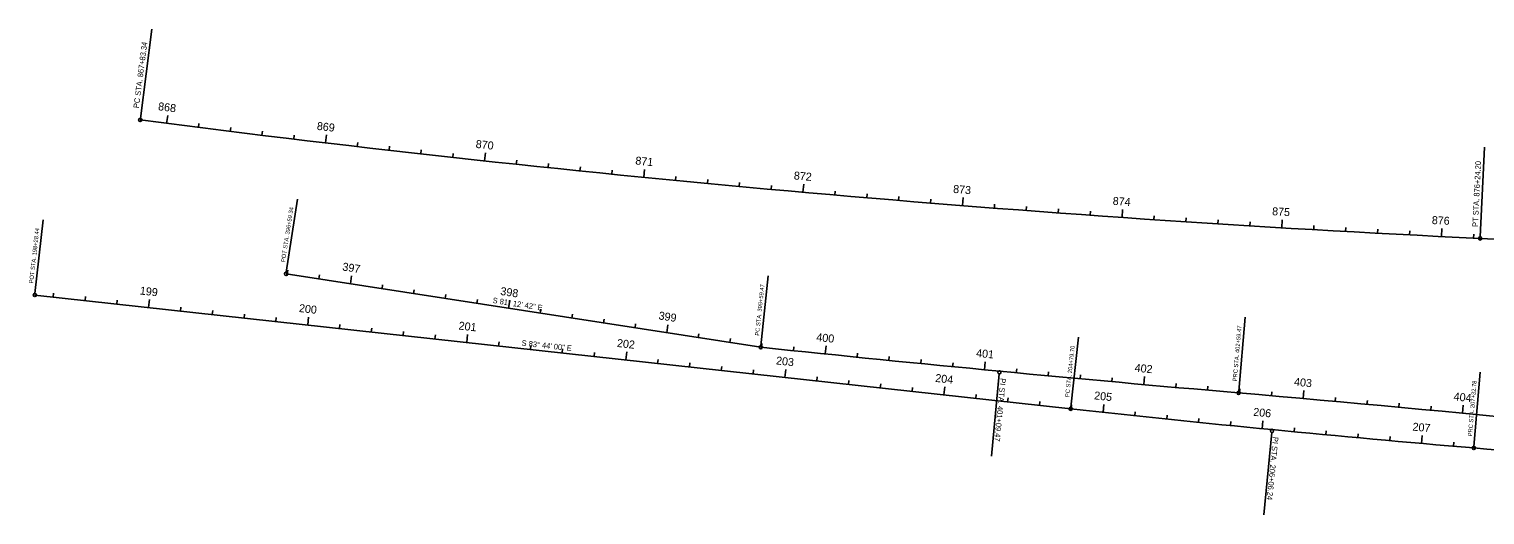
# Model space of a CAD drawing. Extents: x 919452 to 931278, y 583254 to 665650.
# Drawn here: x 925159 to 926069, y 636745 to 637048 of the extents above; entities that cross this region are included whole.
import ezdxf

# ---------------------------------------------------------------- set-up
doc = ezdxf.new("R2010")
doc.units = 0
for name, color, linetype in [('CLConst_dp', 7, 'Continuous'), ('CurveDataLabel_dp', 7, 'Continuous'), ('StationTicL_dp', 7, 'Continuous'), ('StationTicS_dp', 7, 'Continuous'), ('TextBLStation', 7, 'Continuous'), ('TextLabel', 7, 'Continuous')]:
    doc.layers.add(name, color=color, linetype=linetype)

msp = doc.modelspace()

# ---------------------------------------------------------------- linework, layer by layer
at = {"layer": 'CLConst_dp'}
for p, q in [((926065.6, 636917.34), (926567.14, 636893.49)), ((925319.39, 636895.17), (925615.99, 636849.32)), ((925162.36, 636881.97), (925809.72, 636810.88))]:
    msp.add_line(p, q, dxfattribs=at)
for centre, radius, start, end in [((926557.14, 647252.26), 10346.6, 262.620616, 267.276979), ((927324.25, 653175.3), 16415.11, 264.026645, 265.073773), ((924651.1, 622161.18), 14714, 83.482815, 85.073773), ((926900.29, 646742.19), 9991, 263.733403, 265.184769), ((925098.46, 625352.94), 11474, 83.891103, 85.184769)]:
    msp.add_arc(centre, radius, start, end, dxfattribs=at)
at = {"layer": 'CurveDataLabel_dp'}
for p, q in [((925228.37, 636992.35), (925235.59, 637048.09)), ((926065.65, 636918.34), (926068.32, 636974.44)), ((925319.54, 636896.16), (925326.6, 636941.84)), ((925162.47, 636882.97), (925167.51, 636928.91)), ((925616.1, 636850.31), (925620.66, 636893.97)), ((925914.72, 636821.82), (925918.71, 636868.12)), ((925809.83, 636811.88), (925814.63, 636855.56)), ((925765.09, 636832.71), (925760.18, 636781.27)), ((926061.7, 636787.44), (926065.61, 636833.85)), ((925935.42, 636796.08), (925930.43, 636744.62))]:
    msp.add_line(p, q, dxfattribs=at)
for centre in [(925228.24, 636991.36), (926065.6, 636917.34), (925319.39, 636895.17), (925162.36, 636881.97), (925615.99, 636849.32), (925765.18, 636833.71), (925914.63, 636820.83), (925809.72, 636810.88), (925935.52, 636797.07), (926061.62, 636786.45)]:
    msp.add_circle(centre, 1, dxfattribs=at)
at = {"layer": 'StationTicL_dp'}
for p, q in [((925244.76, 636989.23), (925245.4, 636994.19)), ((925344.01, 636977.02), (925344.6, 636981.99)), ((925443.38, 636965.78), (925443.92, 636970.75)), ((925542.85, 636955.5), (925543.34, 636960.47)), ((925642.41, 636946.17), (925642.86, 636951.15)), ((925742.06, 636937.81), (925742.46, 636942.8)), ((925841.79, 636930.42), (925842.13, 636935.41)), ((925941.58, 636923.99), (925941.88, 636928.98)), ((926041.43, 636918.52), (926041.68, 636923.51)), ((925359.57, 636888.96), (925360.34, 636893.9)), ((925233.49, 636874.16), (925234.04, 636879.13)), ((925458.4, 636873.68), (925459.16, 636878.62)), ((925332.89, 636863.25), (925333.44, 636868.22)), ((925432.3, 636852.33), (925432.84, 636857.3)), ((925557.22, 636858.41), (925557.99, 636863.35)), ((925531.7, 636841.41), (925532.24, 636846.38)), ((925656.31, 636845.15), (925656.82, 636850.13)), ((925755.82, 636835.29), (925756.3, 636840.27)), ((925631.1, 636830.5), (925631.65, 636835.47)), ((925855.39, 636826.04), (925855.84, 636831.02)), ((925730.5, 636819.58), (925731.05, 636824.55)), ((925955.01, 636817.29), (925955.45, 636822.27)), ((925829.91, 636808.69), (925830.44, 636813.66)), ((926054.59, 636808.09), (926055.06, 636813.07)), ((925929.39, 636798.47), (925929.87, 636803.45)), ((926028.96, 636789.25), (926029.39, 636794.23))]:
    msp.add_line(p, q, dxfattribs=at)
at = {"layer": 'StationTicS_dp'}
for p, q in [((925264.6, 636986.71), (925264.92, 636989.19)), ((925284.45, 636984.23), (925284.76, 636986.71)), ((925304.3, 636981.79), (925304.6, 636984.27)), ((925324.16, 636979.39), (925324.45, 636981.87)), ((925363.88, 636974.7), (925364.17, 636977.18)), ((925383.75, 636972.41), (925384.03, 636974.9)), ((925403.62, 636970.16), (925403.9, 636972.65)), ((925423.5, 636967.95), (925423.77, 636970.44)), ((925463.27, 636963.65), (925463.53, 636966.13)), ((925483.16, 636961.55), (925483.42, 636964.04)), ((925503.05, 636959.49), (925503.3, 636961.98)), ((925522.95, 636957.48), (925523.2, 636959.96)), ((925562.76, 636953.55), (925563, 636956.04)), ((925582.66, 636951.65), (925582.9, 636954.14)), ((925602.58, 636949.79), (925602.81, 636952.28)), ((925622.49, 636947.96), (925622.72, 636950.45)), ((925662.34, 636944.43), (925662.55, 636946.92)), ((925682.26, 636942.71), (925682.48, 636945.21)), ((925702.19, 636941.04), (925702.4, 636943.53)), ((925722.13, 636939.41), (925722.33, 636941.9)), ((925762, 636936.26), (925762.19, 636938.75)), ((925781.95, 636934.74), (925782.13, 636937.23)), ((925801.89, 636933.26), (925802.07, 636935.75)), ((925821.84, 636931.82), (925822.02, 636934.31)), ((925861.74, 636929.06), (925861.91, 636931.55)), ((925881.7, 636927.73), (925881.86, 636930.23)), ((925901.66, 636926.44), (925901.82, 636928.94)), ((925921.62, 636925.2), (925921.77, 636927.69)), ((925961.55, 636922.82), (925961.69, 636925.31)), ((925981.52, 636921.68), (925981.65, 636924.18)), ((926001.49, 636920.59), (926001.62, 636923.09)), ((926021.46, 636919.54), (926021.59, 636922.03)), ((926061.41, 636917.54), (926061.53, 636920.04)), ((925320.04, 636895.07), (925320.42, 636897.54)), ((925339.81, 636892.02), (925340.19, 636894.49)), ((925173.85, 636880.71), (925174.12, 636883.2)), ((925379.34, 636885.91), (925379.72, 636888.38)), ((925399.1, 636882.85), (925399.48, 636885.32)), ((925193.73, 636878.53), (925194, 636881.01)), ((925213.61, 636876.34), (925213.88, 636878.83)), ((925253.37, 636871.98), (925253.65, 636874.46)), ((925418.87, 636879.79), (925419.25, 636882.27)), ((925438.63, 636876.74), (925439.01, 636879.21)), ((925273.25, 636869.79), (925273.53, 636872.28)), ((925293.13, 636867.61), (925293.41, 636870.1)), ((925313.01, 636865.43), (925313.29, 636867.91)), ((925478.16, 636870.63), (925478.54, 636873.1)), ((925497.93, 636867.57), (925498.31, 636870.04)), ((925517.69, 636864.52), (925518.08, 636866.99)), ((925352.77, 636861.06), (925353.05, 636863.55)), ((925372.66, 636858.88), (925372.93, 636861.36)), ((925392.54, 636856.7), (925392.81, 636859.18)), ((925412.42, 636854.51), (925412.69, 636857)), ((925537.46, 636861.46), (925537.84, 636863.93)), ((925576.99, 636855.35), (925577.37, 636857.82)), ((925452.18, 636850.15), (925452.45, 636852.63)), ((925472.06, 636847.96), (925472.33, 636850.45)), ((925491.94, 636845.78), (925492.21, 636848.27)), ((925596.75, 636852.29), (925597.14, 636854.76)), ((925616.52, 636849.26), (925616.78, 636851.75)), ((925636.42, 636847.2), (925636.67, 636849.68)), ((925511.82, 636843.6), (925512.09, 636846.08)), ((925551.58, 636839.23), (925551.85, 636841.72)), ((925571.46, 636837.05), (925571.73, 636839.53)), ((925591.34, 636834.86), (925591.61, 636837.35)), ((925676.21, 636843.13), (925676.46, 636845.62)), ((925696.11, 636841.14), (925696.36, 636843.62)), ((925716.01, 636839.16), (925716.26, 636841.65)), ((925735.92, 636837.22), (925736.16, 636839.7)), ((925611.22, 636832.68), (925611.49, 636835.17)), ((925650.98, 636828.32), (925651.26, 636830.8)), ((925670.86, 636826.13), (925671.14, 636828.62)), ((925775.73, 636833.39), (925775.97, 636835.88)), ((925795.64, 636831.52), (925795.88, 636834.01)), ((925815.56, 636829.67), (925815.79, 636832.16)), ((925835.48, 636827.84), (925835.7, 636830.33)), ((925690.74, 636823.95), (925691.02, 636826.43)), ((925710.62, 636821.77), (925710.9, 636824.25)), ((925750.38, 636817.4), (925750.66, 636819.89)), ((925875.32, 636824.26), (925875.54, 636826.75)), ((925895.24, 636822.51), (925895.46, 636825)), ((925915.16, 636820.78), (925915.38, 636823.27)), ((925935.09, 636819.05), (925935.31, 636821.54)), ((925770.27, 636815.22), (925770.54, 636817.7)), ((925790.15, 636813.03), (925790.42, 636815.52)), ((925810.03, 636810.85), (925810.3, 636813.34)), ((925974.93, 636815.51), (925975.16, 636818)), ((925994.85, 636813.69), (925995.08, 636816.18)), ((926014.76, 636811.85), (926015, 636814.34)), ((926034.68, 636809.99), (926034.91, 636812.47)), ((925849.8, 636806.57), (925850.06, 636809.05)), ((925869.69, 636804.48), (925869.94, 636806.97)), ((925889.58, 636802.44), (925889.84, 636804.93)), ((925909.48, 636800.44), (925909.73, 636802.92)), ((925949.29, 636796.55), (925949.53, 636799.04)), ((925969.2, 636794.67), (925969.44, 636797.15)), ((925989.12, 636792.82), (925989.35, 636795.31)), ((926009.04, 636791.02), (926009.26, 636793.51)), ((926048.88, 636787.53), (926049.1, 636790.02))]:
    msp.add_line(p, q, dxfattribs=at)

# ---------------------------------------------------------------- texts
at = {"layer": 'CurveDataLabel_dp'}
for s, height, rotation, p in [('PC STA. 867+83.34', 3.5, 82.62062, (925227.4, 636998.52)), ('PT STA. 876+24.20', 3.5, 87.27698, (926064.18, 636924.42)), ('POT STA. 396+59.34', 2.625, 81.2117, (925318.73, 636902.36)), ('POT STA. 198+28.44', 2.625, 83.7334, (925161.38, 636889.12)), ('PC STA. 399+59.47', 2.625, 84.02664, (925614.98, 636856.46)), ('PRC STA. 402+59.47', 2.625, 85.07377, (925913.49, 636827.95)), ('PC STA. 204+79.70', 2.625, 83.7334, (925808.75, 636818.03)), ('PI STA. 401+09.47', 3.5, 264.55021, (925765.72, 636830.14)), ('PRC STA. 207+32.78', 2.625, 85.18477, (926060.46, 636793.57)), ('PI STA. 206+06.24', 3.5, 264.45909, (925936.05, 636793.5))]:
    msp.add_text(s, height=height, rotation=rotation, dxfattribs=at).set_placement(p)
at = {"layer": 'TextBLStation'}
for s, rotation, p in [('868', 352.71287, (925239.2, 636997.5)), ('869', 353.26664, (925338.41, 636985.24)), ('870', 353.8204, (925437.7, 636973.94)), ('871', 354.37417, (925537.48, 636963.56)), ('872', 354.92793, (925636.52, 636954.23)), ('873', 355.48169, (925736.09, 636945.81)), ('874', 356.03546, (925835.84, 636938.35)), ('875', 356.58922, (925935.47, 636931.86)), ('876', 357.14299, (926035.28, 636926.34)), ('397', 351.2117, (925354.32, 636897.36)), ('199', 353.7334, (925227.82, 636882.33)), ('398', 351.2117, (925453.05, 636882.1)), ('200', 353.7334, (925327.23, 636871.41)), ('201', 353.7334, (925427.02, 636860.45)), ('399', 351.2117, (925551.91, 636866.82)), ('400', 354.16813, (925650.58, 636853.28)), ('202', 353.7334, (925525.97, 636849.59)), ('401', 354.51717, (925750.43, 636843.35)), ('203', 353.7334, (925625.37, 636838.67)), ('402', 354.86621, (925849.51, 636834.1)), ('204', 353.7334, (925724.87, 636827.75)), ('403', 354.91594, (925949.11, 636825.35)), ('205', 353.84984, (925824.18, 636816.85)), ('404', 354.52654, (926048.84, 636816.18)), ('206', 354.42332, (925923.61, 636806.57)), ('207', 354.99679, (926023.16, 636797.29))]:
    msp.add_text(s, height=5, rotation=rotation, dxfattribs=at).set_placement(p)
at = {"layer": 'TextLabel'}
for s, rotation, p in [('S 81%%d 12\' 42" E', 351.2117, (925448.27, 636877.02)), ('S 83%%d 44\' 00" E', 353.7334, (925466.43, 636850.34))]:
    msp.add_text(s, height=3.5, rotation=rotation, dxfattribs=at).set_placement(p)

doc.saveas('drawing.dxf')
